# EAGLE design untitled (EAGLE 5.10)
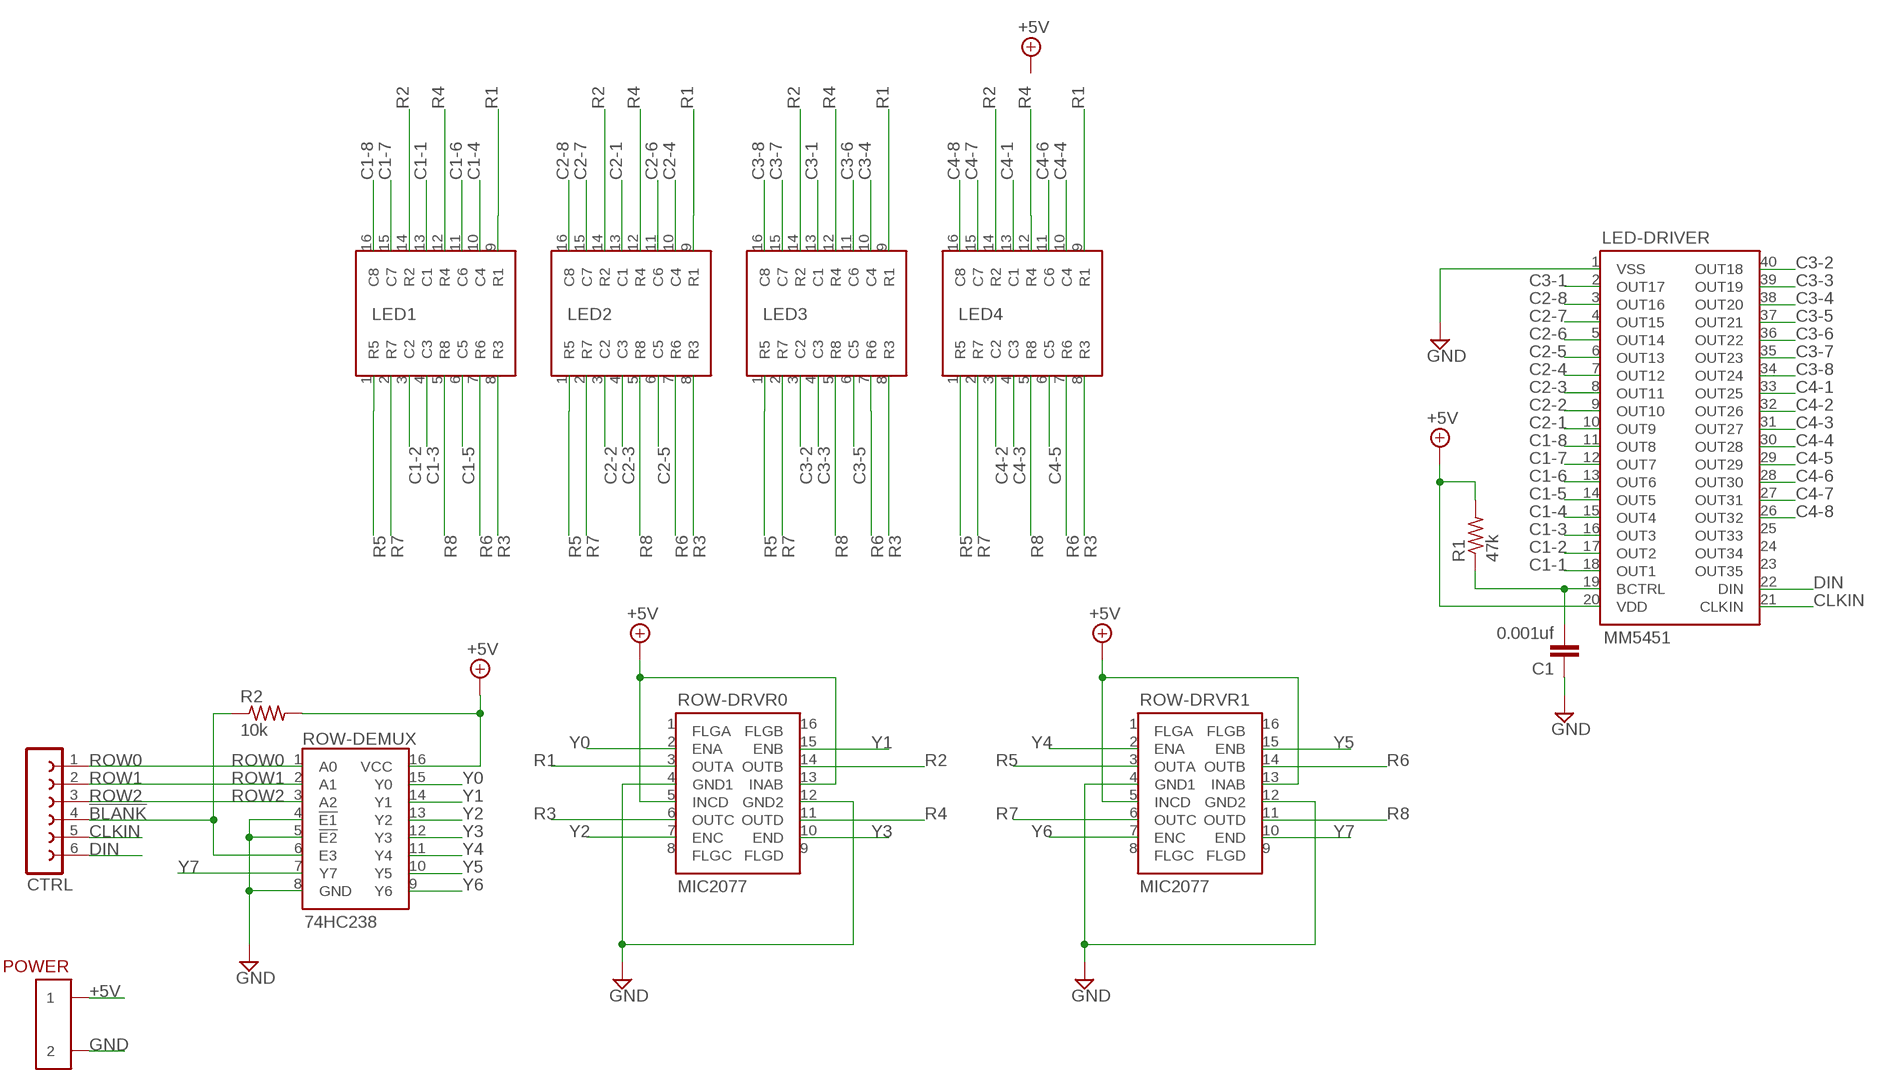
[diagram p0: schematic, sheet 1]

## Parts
C1  0.001uf  C-EU050-024X044  [C050-024X044]
CTRL  FE06-1  [FE06]
LED1  LED-MATRIX-8X8  [DIL16-6]
LED2  LED-MATRIX-8X8  [DIL16-6]
LED3  LED-MATRIX-8X8  [DIL16-6]
LED4  LED-MATRIX-8X8  [DIL16-6]
LED-DRIVER  MM5451  [DIL40-6]
POWER  SCREW-CLAMP-1.5  [SCREW-CLAMP-1.5]
R1  47k  R-US_0207/7  [0207/7]
R2  10k  R-US_M1206  [M1206]
ROW-DEMUX  74HC238  [DIL16-3]
ROW-DRVR0  MIC2077  [SO16]
ROW-DRVR1  MIC2077  [SO16]

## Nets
!BLANK: CTRL.4 R2.1 ROW-DEMUX.6(E3)
+5V: LED-DRIVER.20(VDD) POWER.1 R1.2 R2.2 ROW-DEMUX.16(VCC) ROW-DRVR0.5(INCD) ROW-DRVR0.13(INAB) ROW-DRVR1.5(INCD) ROW-DRVR1.13(INAB)
C1-1: LED1.13(C1) LED-DRIVER.18(OUT1)
C1-2: LED1.3(C2) LED-DRIVER.17(OUT2)
C1-3: LED1.4(C3) LED-DRIVER.16(OUT3)
C1-4: LED1.10(C4) LED-DRIVER.15(OUT4)
C1-5: LED1.6(C5) LED-DRIVER.14(OUT5)
C1-6: LED1.11(C6) LED-DRIVER.13(OUT6)
C1-7: LED1.15(C7) LED-DRIVER.12(OUT7)
C1-8: LED1.16(C8) LED-DRIVER.11(OUT8)
C2-1: LED2.13(C1) LED-DRIVER.10(OUT9)
C2-2: LED2.3(C2) LED-DRIVER.9(OUT10)
C2-3: LED2.4(C3) LED-DRIVER.8(OUT11)
C2-4: LED2.10(C4) LED-DRIVER.7(OUT12)
C2-5: LED2.6(C5) LED-DRIVER.6(OUT13)
C2-6: LED2.11(C6) LED-DRIVER.5(OUT14)
C2-7: LED2.15(C7) LED-DRIVER.4(OUT15)
C2-8: LED2.16(C8) LED-DRIVER.3(OUT16)
C3-1: LED3.13(C1) LED-DRIVER.2(OUT17)
C3-2: LED3.3(C2) LED-DRIVER.40(OUT18)
C3-3: LED3.4(C3) LED-DRIVER.39(OUT19)
C3-4: LED3.10(C4) LED-DRIVER.38(OUT20)
C3-5: LED3.6(C5) LED-DRIVER.37(OUT21)
C3-6: LED3.11(C6) LED-DRIVER.36(OUT22)
C3-7: LED3.15(C7) LED-DRIVER.35(OUT23)
C3-8: LED3.16(C8) LED-DRIVER.34(OUT24)
C4-1: LED4.13(C1) LED-DRIVER.33(OUT25)
C4-2: LED4.3(C2) LED-DRIVER.32(OUT26)
C4-3: LED4.4(C3) LED-DRIVER.31(OUT27)
C4-4: LED4.10(C4) LED-DRIVER.30(OUT28)
C4-5: LED4.6(C5) LED-DRIVER.29(OUT29)
C4-6: LED4.11(C6) LED-DRIVER.28(OUT30)
C4-7: LED4.15(C7) LED-DRIVER.27(OUT31)
C4-8: LED4.16(C8) LED-DRIVER.26(OUT32)
CLKIN: CTRL.5 LED-DRIVER.21(CLKIN)
DIN: CTRL.6 LED-DRIVER.22(DIN)
GND: C1.1 LED-DRIVER.1(VSS) POWER.2 ROW-DEMUX.4(!E1) ROW-DEMUX.5(!E2) ROW-DEMUX.8(GND) ROW-DRVR0.4(GND1) ROW-DRVR0.12(GND2) ROW-DRVR1.4(GND1) ROW-DRVR1.12(GND2)
N$1: C1.2 LED-DRIVER.19(BCTRL) R1.1
R1: LED1.9(R1) LED2.9(R1) LED3.9(R1) LED4.9(R1) ROW-DRVR0.3(OUTA)
R2: LED1.14(R2) LED2.14(R2) LED3.14(R2) LED4.14(R2) ROW-DRVR0.14(OUTB)
R3: LED1.8(R3) LED2.8(R3) LED3.8(R3) LED4.8(R3) ROW-DRVR0.6(OUTC)
R4: LED1.12(R4) LED2.12(R4) LED3.12(R4) LED4.12(R4) ROW-DRVR0.11(OUTD)
R5: LED1.1(R5) LED2.1(R5) LED3.1(R5) LED4.1(R5) ROW-DRVR1.3(OUTA)
R6: LED1.7(R6) LED2.7(R6) LED3.7(R6) LED4.7(R6) ROW-DRVR1.14(OUTB)
R7: LED1.2(R7) LED2.2(R7) LED3.2(R7) LED4.2(R7) ROW-DRVR1.6(OUTC)
R8: LED1.5(R8) LED2.5(R8) LED3.5(R8) LED4.5(R8) ROW-DRVR1.11(OUTD)
ROW0: CTRL.1 ROW-DEMUX.1(A0)
ROW1: CTRL.2 ROW-DEMUX.2(A1)
ROW2: CTRL.3 ROW-DEMUX.3(A2)
Y0: ROW-DEMUX.15(Y0) ROW-DRVR0.2(ENA)
Y1: ROW-DEMUX.14(Y1) ROW-DRVR0.15(ENB)
Y2: ROW-DEMUX.13(Y2) ROW-DRVR0.7(ENC)
Y3: ROW-DEMUX.12(Y3) ROW-DRVR0.10(END)
Y4: ROW-DEMUX.11(Y4) ROW-DRVR1.2(ENA)
Y5: ROW-DEMUX.10(Y5) ROW-DRVR1.15(ENB)
Y6: ROW-DEMUX.9(Y6) ROW-DRVR1.7(ENC)
Y7: ROW-DEMUX.7(Y7) ROW-DRVR1.10(END)
Unconnected: LED-DRIVER.23(OUT35) LED-DRIVER.24(OUT34) LED-DRIVER.25(OUT33) ROW-DRVR0.1(FLGA) ROW-DRVR0.8(FLGC) ROW-DRVR0.9(FLGD) ROW-DRVR0.16(FLGB) ROW-DRVR1.1(FLGA) ROW-DRVR1.8(FLGC) ROW-DRVR1.9(FLGD) ROW-DRVR1.16(FLGB)

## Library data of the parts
C1 = rcl:C-EU: CAPACITOR, European symbol
CTRL = con-lsta:FE06-1: FEMALE HEADER
LED1-LED4 = trl:LED-MATRIX-8X8
LED-DRIVER = trl:MM5451
POWER = trl:SCREW-CLAMP-1.5
R1 R2 = resistor:R-US_: RESISTOR, American symbol
ROW-DEMUX = trl:74HC238
ROW-DRVR0 ROW-DRVR1 = trl:MIC2077

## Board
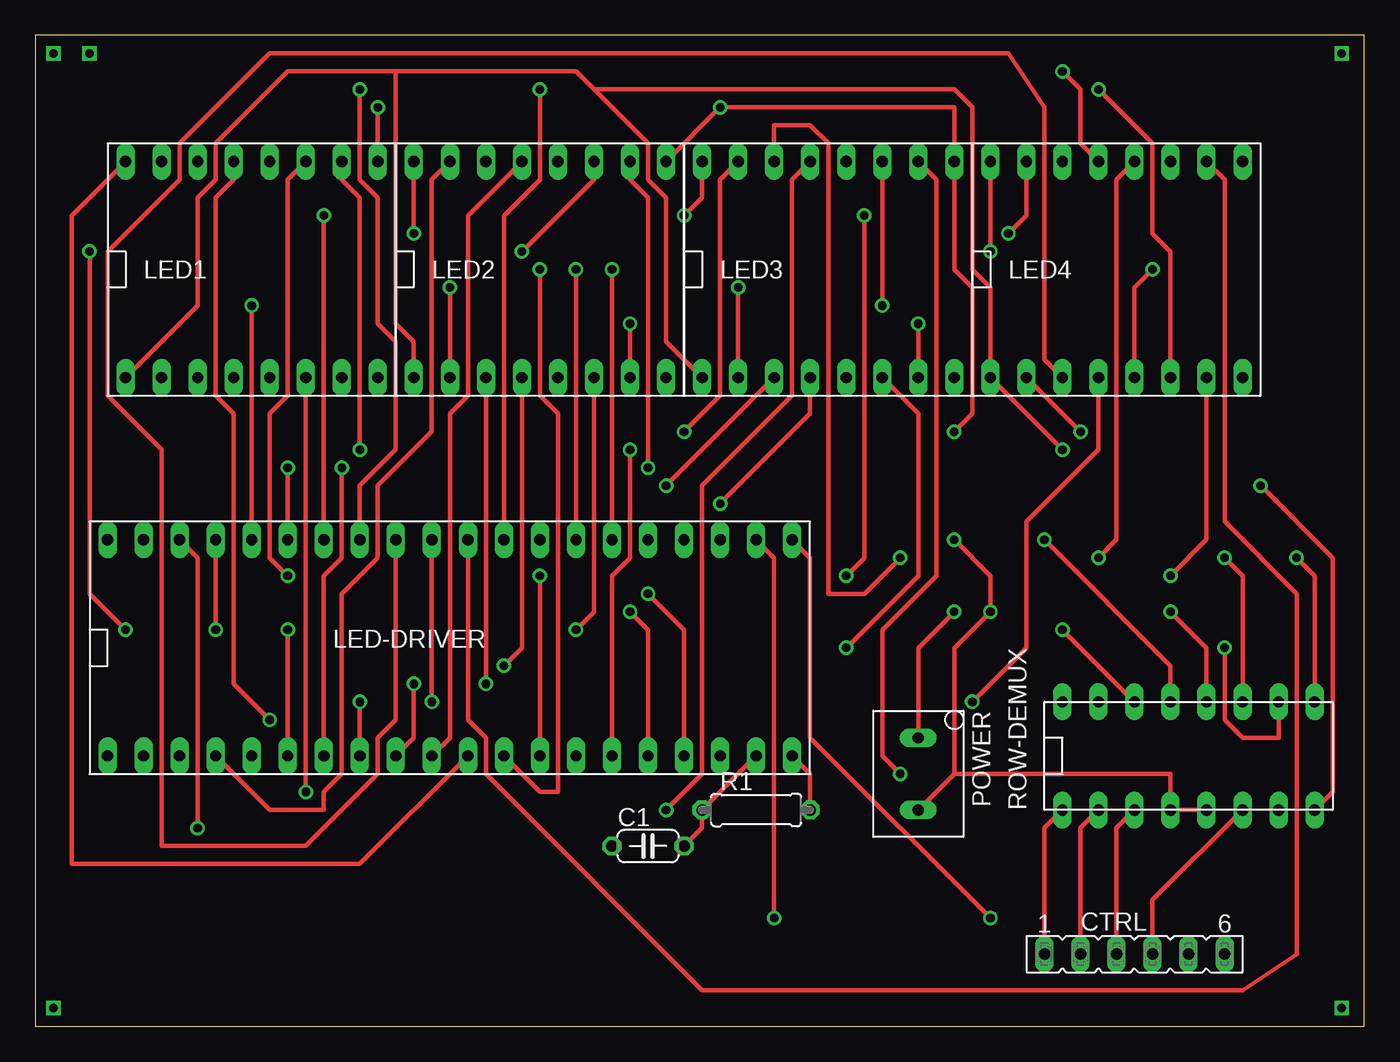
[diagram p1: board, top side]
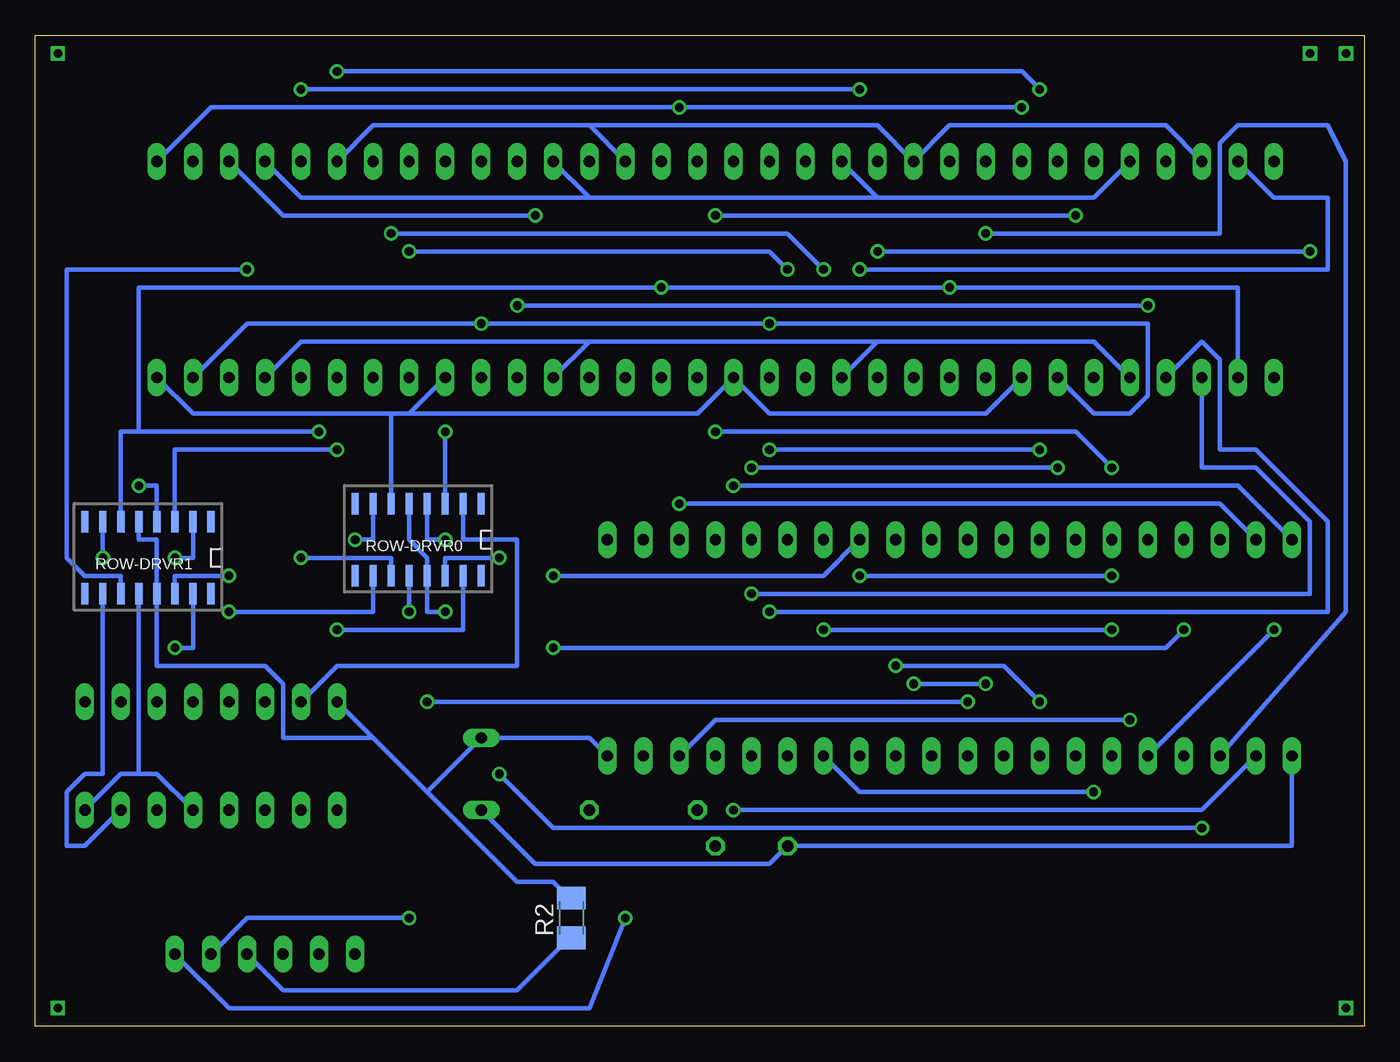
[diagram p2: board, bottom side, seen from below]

Size 93.65 x 69.84 mm. Coordinates in mm from the lower left corner, seen from the top.
Outline: 0,0 93.65,0 93.65,69.84 0,69.84 0,0
Copper layers (1*16): Top 0.035mm / dielectric 1.5mm / Bottom 0.035mm
Design rules "default *": minimum track width 12mil, minimum drill 24mil, track to track 10mil, track to pad 10mil, pad to pad 10mil, via to via 10mil, smd to smd 10mil, copper to edge 40mil, drill to drill 10mil, minimum pad ring 10mil, minimum via ring 8mil, stop-mask expansion 4mil, vias tented up to drill 0mil, thermal gap 10mil

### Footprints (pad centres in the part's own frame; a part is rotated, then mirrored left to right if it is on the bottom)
C050-024X044 = drill 0.813 octagon: 1 -2.54,0; 2 2.54,0
FE06 = drill 0.813 long: 1 -6.35,0; 2 -3.81,0; 3 -1.27,0; 4 1.27,0; 5 3.81,0; 6 6.35,0
DIL16-6 = drill 0.8 long: 1 -8.89,-7.62; 2 -6.35,-7.62; 3 -3.81,-7.62; 4 -1.27,-7.62; 5 1.27,-7.62; 6 3.81,-7.62; 7 6.35,-7.62; 8 8.89,-7.62; 9 8.89,7.62; 10 6.35,7.62; 11 3.81,7.62; 12 1.27,7.62; 13 -1.27,7.62; 14 -3.81,7.62; 15 -6.35,7.62; 16 -8.89,7.62
DIL40-6 = drill 0.8 long: 1 -7.62,24.13; 2 -7.62,21.59; 3 -7.62,19.05; 4 -7.62,16.51; 5 -7.62,13.97; 6 -7.62,11.43; 7 -7.62,8.89; 8 -7.62,6.35; 9 -7.62,3.81; 10 -7.62,1.27; 11 -7.62,-1.27; 12 -7.62,-3.81; 13 -7.62,-6.35; 14 -7.62,-8.89; 15 -7.62,-11.43; 16 -7.62,-13.97; 17 -7.62,-16.51; 18 -7.62,-19.05; 19 -7.62,-21.59; 20 -7.62,-24.13; 21 7.62,-24.13; 22 7.62,-21.59; 23 7.62,-19.05; 24 7.62,-16.51; 25 7.62,-13.97; 26 7.62,-11.43; 27 7.62,-8.89; 28 7.62,-6.35; 29 7.62,-3.81; 30 7.62,-1.27; 31 7.62,1.27; 32 7.62,3.81; 33 7.62,6.35; 34 7.62,8.89; 35 7.62,11.43; 36 7.62,13.97; 37 7.62,16.51; 38 7.62,19.05; 39 7.62,21.59; 40 7.62,24.13
SCREW-CLAMP-1.5 = drill 0.8 long: 1 -1.27,0; 2 3.81,0
0207/7 = drill 0.813 octagon: 1 -3.81,0; 2 3.81,0
M1206 = smd 1.6 x 2: 1 -1.4,0; 2 1.4,0
DIL16-3 = drill 0.8 long: 1 -3.81,8.89; 2 -3.81,6.35; 3 -3.81,3.81; 4 -3.81,1.27; 5 -3.81,-1.27; 6 -3.81,-3.81; 7 -3.81,-6.35; 8 -3.81,-8.89; 9 3.81,-8.89; 10 3.81,-6.35; 11 3.81,-3.81; 12 3.81,-1.27; 13 3.81,1.27; 14 3.81,3.81; 15 3.81,6.35; 16 3.81,8.89
SO16 = smd 0.508 x 1.524: 1 -3.81,-2.54; 2 -2.54,-2.54; 3 -1.27,-2.54; 4 0,-2.54; 5 1.27,-2.54; 6 2.54,-2.54; 7 3.81,-2.54; 8 5.08,-2.54; 9 5.08,2.54; 10 3.81,2.54; 11 2.54,2.54; 12 1.27,2.54; 13 0,2.54; 14 -1.27,2.54; 15 -2.54,2.54; 16 -3.81,2.54

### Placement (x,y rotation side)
C1  43.18,12.7 0 top
CTRL  77.47,5.08 0 top
LED1  15.24,53.34 0 top
LED2  35.56,53.34 0 top
LED3  55.88,53.34 0 top
LED4  76.2,53.34 0 top
LED-DRIVER  29.21,26.67 90 top
POWER  62.23,19.05 270 top
R1  50.8,15.24 0 top
R2  55.88,7.62 90 bottom
ROW-DEMUX  81.28,19.05 90 top
ROW-DRVR0  66.04,34.29 180 bottom
ROW-DRVR1  85.09,33.02 180 bottom

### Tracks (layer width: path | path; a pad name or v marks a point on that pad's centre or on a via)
!BLANK
  Top 0.305: ROW-DEMUX.6 78.74,8.89 CTRL.4
  Bottom 0.305: CTRL.4 76.2,2.54 59.69,2.54 55.88,6.35 R2.1
+5V  (via drill 0.61)
  Top 0.305: LED-DRIVER.20 54.61,17.78 R1.2 | v64.77,29.21 62.23,26.67 POWER.1
  Bottom 0.305: ROW-DRVR0.5 67.31,34.29 66.04,33.02 ROW-DRVR0.13 66.04,29.21 v64.77,29.21 | ROW-DRVR1.5 86.36,34.29 85.09,34.29 ROW-DRVR1.13 85.09,25.4 77.47,25.4 76.2,24.13 76.2,20.32 69.85,20.32 | 69.85,20.32 ROW-DEMUX.16 | 66.04,16.51 69.85,20.32 | 66.04,16.51 59.69,10.16 57.15,10.16 55.88,8.89 R2.2 | 66.04,16.51 POWER.1 54.61,20.32 LED-DRIVER.20
C1-1  (via drill 0.61)
  Top 0.305: v16.51,21.59 13.97,24.13 13.97,43.18 12.7,44.45 12.7,58.42 13.97,59.69 LED1.13
  Bottom 0.305: LED-DRIVER.18 45.72,21.59 v16.51,21.59
C1-2  (via drill 0.61)
  Top 0.305: v43.18,30.48 45.72,27.94 LED-DRIVER.17
  Bottom 0.305: LED1.3 11.43,39.37 7.62,39.37 3.81,35.56 3.81,30.48 v43.18,30.48
C1-3  (via drill 0.61)
  Top 0.305: v41.91,29.21 43.18,27.94 LED-DRIVER.16
  Bottom 0.305: LED1.4 11.43,48.26 10.16,46.99 10.16,40.64 7.62,40.64 2.54,35.56 2.54,29.21 v41.91,29.21
C1-4  (via drill 0.61)
  Top 0.305: LED-DRIVER.15 40.64,31.75 41.91,33.02 v41.91,40.64 | v22.86,40.64 22.86,58.42 21.59,59.69 LED1.10
  Bottom 0.305: v41.91,40.64 v22.86,40.64
C1-5  (via drill 0.61)
  Top 0.305: v19.05,16.51 LED1.6
  Bottom 0.305: LED-DRIVER.14 35.56,16.51 v19.05,16.51
C1-6  (via drill 0.61)
  Top 0.305: v35.56,31.75 LED-DRIVER.13 | v17.78,31.75 16.51,33.02 16.51,43.18 17.78,44.45 17.78,59.69 LED1.11
  Bottom 0.305: v17.78,31.75 v35.56,31.75
C1-7  (via drill 0.61)
  Top 0.305: LED-DRIVER.12 35.56,16.51 36.83,16.51 36.83,43.18 35.56,44.45 v35.56,53.34
  Bottom 0.305: v35.56,53.34 2.54,53.34 2.54,58.42 6.35,58.42 LED1.15
C1-8
  Top 0.305: LED-DRIVER.11 22.86,11.43 2.54,11.43 2.54,57.15 LED1.16
C2-1
  Top 0.305: LED-DRIVER.10 29.21,20.32 29.21,43.18 30.48,44.45 30.48,57.15 LED2.13
C2-2  (via drill 0.61)
  Top 0.305: LED-DRIVER.9 26.67,20.32 v26.67,24.13 | v31.75,24.13 LED2.3
  Bottom 0.305: v26.67,24.13 v31.75,24.13
C2-3  (via drill 0.61)
  Top 0.305: LED-DRIVER.8 v22.86,22.86 | v33.02,25.4 34.29,26.67 LED2.4
  Bottom 0.305: v22.86,22.86 25.4,25.4 v33.02,25.4
C2-4  (via drill 0.61)
  Top 0.305: LED-DRIVER.7 20.32,31.75 21.59,33.02 v21.59,39.37 | v43.18,39.37 43.18,58.42 41.91,59.69 LED2.10
  Bottom 0.305: v21.59,39.37 v43.18,39.37
C2-5  (via drill 0.61)
  Top 0.305: LED-DRIVER.6 v17.78,27.94 | v38.1,27.94 39.37,29.21 LED2.6
  Bottom 0.305: v17.78,27.94 v38.1,27.94
C2-6  (via drill 0.61)
  Top 0.305: v6.35,27.94 3.81,30.48 v3.81,54.61 | v34.29,54.61 39.37,59.69 LED2.11
  Bottom 0.305: LED-DRIVER.5 v6.35,27.94 | v3.81,54.61 v34.29,54.61
C2-7
  Top 0.305: LED-DRIVER.4 16.51,15.24 20.32,15.24 20.32,16.51 21.59,17.78 21.59,30.48 24.13,33.02 24.13,38.1 27.94,41.91 27.94,59.69 LED2.15
C2-8  (via drill 0.61)
  Top 0.305: v26.67,55.88 LED2.16
  Bottom 0.305: LED-DRIVER.3 1.27,29.21 1.27,60.96 2.54,63.5 8.89,63.5 10.16,62.23 10.16,55.88 v26.67,55.88
C3-1  (via drill 0.61)
  Top 0.305: v44.45,15.24 46.99,17.78 46.99,38.1 53.34,44.45 53.34,59.69 LED3.13
  Bottom 0.305: LED-DRIVER.2 11.43,15.24 v44.45,15.24
C3-2  (via drill 0.61)
  Top 0.305: v44.45,38.1 LED3.3
  Bottom 0.305: LED-DRIVER.40 8.89,38.1 v44.45,38.1
C3-3  (via drill 0.61)
  Top 0.305: v48.26,36.83 54.61,43.18 LED3.4
  Bottom 0.305: LED-DRIVER.39 10.16,36.83 v48.26,36.83
C3-4  (via drill 0.61)
  Top 0.305: LED-DRIVER.38 11.43,33.02 v11.43,13.97 | v60.96,17.78 59.69,19.05 59.69,27.94 63.5,31.75 63.5,59.69 LED3.10
  Bottom 0.305: v11.43,13.97 57.15,13.97 v60.96,17.78
C3-5  (via drill 0.61)
  Top 0.305: v12.7,27.94 LED-DRIVER.37 | v57.15,26.67 62.23,31.75 62.23,43.18 LED3.6
  Bottom 0.305: v12.7,27.94 13.97,26.67 v57.15,26.67
C3-6  (via drill 0.61)
  Top 0.305: LED-DRIVER.36 v15.24,50.8 | v59.69,50.8 LED3.11
  Bottom 0.305: v15.24,50.8 v59.69,50.8
C3-7  (via drill 0.61)
  Top 0.305: LED-DRIVER.35 v17.78,39.37 | v45.72,41.91 48.26,44.45 48.26,59.69 LED3.15
  Bottom 0.305: v17.78,39.37 20.32,41.91 v45.72,41.91
C3-8  (via drill 0.61)
  Top 0.305: LED-DRIVER.34 v20.32,57.15 | v45.72,57.15 46.99,58.42 LED3.16
  Bottom 0.305: v20.32,57.15 v45.72,57.15
C4-1  (via drill 0.61)
  Top 0.305: LED-DRIVER.33 22.86,38.1 25.4,40.64 25.4,48.26 24.13,49.53 24.13,58.42 22.86,59.69 v22.86,66.04 | v72.39,67.31 73.66,66.04 73.66,62.23 LED4.13
  Bottom 0.305: v22.86,66.04 24.13,67.31 v72.39,67.31
C4-2
  Top 0.305: LED-DRIVER.32 25.4,21.59 24.13,20.32 24.13,17.78 19.05,12.7 8.89,12.7 8.89,40.64 5.08,44.45 5.08,54.61 10.16,59.69 10.16,62.23 16.51,68.58 68.58,68.58 71.12,64.77 71.12,46.99 LED4.3
C4-3  (via drill 0.61)
  Top 0.305: v27.94,22.86 LED-DRIVER.31 | v66.04,22.86 69.85,26.67 69.85,35.56 74.93,40.64 LED4.4
  Bottom 0.305: v27.94,22.86 v66.04,22.86
C4-4
  Top 0.305: LED-DRIVER.30 30.48,21.59 31.75,20.32 31.75,17.78 46.99,2.54 85.09,2.54 88.9,5.08 88.9,30.48 83.82,35.56 83.82,59.69 LED4.10
C4-5  (via drill 0.61)
  Top 0.305: LED-DRIVER.29 33.02,57.15 35.56,59.69 v35.56,66.04 | v74.93,66.04 78.74,62.23 78.74,55.88 80.01,54.61 LED4.6
  Bottom 0.305: v35.56,66.04 v74.93,66.04
C4-6  (via drill 0.61)
  Top 0.305: v57.15,31.75 58.42,33.02 v58.42,57.15
  Bottom 0.305: LED-DRIVER.28 38.1,31.75 v57.15,31.75 | v58.42,57.15 76.2,57.15 LED4.11
C4-7  (via drill 0.61)
  Top 0.305: LED-DRIVER.27 v38.1,53.34 | v68.58,55.88 69.85,57.15 LED4.15
  Bottom 0.305: v38.1,53.34 40.64,55.88 v68.58,55.88
C4-8  (via drill 0.61)
  Top 0.305: LED-DRIVER.26 v40.64,53.34 | v67.31,54.61 LED4.16
  Bottom 0.305: v40.64,53.34 41.91,54.61 v67.31,54.61
CLKIN  (via drill 0.61)
  Top 0.305: LED-DRIVER.21 54.61,33.02 54.61,20.32 v67.31,7.62
  Bottom 0.305: v67.31,7.62 78.74,7.62 CTRL.5
DIN  (via drill 0.61)
  Top 0.305: LED-DRIVER.22 52.07,33.02 v52.07,7.62
  Bottom 0.305: v52.07,7.62 54.61,1.27 80.01,1.27 CTRL.6
GND  (via drill 0.61)
  Top 0.305: 64.77,17.78 64.77,26.67 v67.31,29.21 ROW-DRVR0.12 v64.77,34.29 | POWER.2 64.77,17.78 | ROW-DEMUX.5 ROW-DEMUX.4 80.01,17.78 64.77,17.78 | v86.36,38.1 91.44,33.02 91.44,16.51 ROW-DEMUX.8
  Bottom 0.305: LED-DRIVER.1 5.08,12.7 C1.1 41.91,11.43 58.42,11.43 POWER.2 | v67.31,29.21 ROW-DRVR0.12 | ROW-DRVR0.4 66.04,34.29 v64.77,34.29 | 86.36,17.78 ROW-DRVR1.12 | 86.36,17.78 85.09,17.78 ROW-DEMUX.5 | ROW-DRVR1.4 85.09,38.1 v86.36,38.1 | 86.36,17.78 87.63,17.78 ROW-DEMUX.8
N$1
  Top 0.305: LED-DRIVER.19 R1.1 46.99,13.97 C1.2
N$5  (via drill 0.6)
  other vias: 1.27,68.58
N$6  (via drill 0.6)
  other vias: 3.81,68.58
N$7  (via drill 0.6)
  other vias: 92.08,68.58
N$8  (via drill 0.6)
  other vias: 92.08,1.27
N$9  (via drill 0.6)
  other vias: 1.27,1.27
R1  (via drill 0.61)
  Top 0.305: v64.77,41.91 66.04,43.18 66.04,52.07 64.77,53.34 LED3.9 64.77,64.77 v48.26,64.77 LED2.9 | LED1.9 v24.13,64.77
  Bottom 0.305: v64.77,41.91 ROW-DRVR0.3 | v24.13,64.77 v48.26,64.77 81.28,64.77 LED4.9
R2  (via drill 0.61)
  Top 0.305: v60.96,33.02 58.42,30.48 55.88,30.48 55.88,62.23 54.61,63.5 52.07,63.5 LED3.14
  Bottom 0.305: LED1.14 13.97,63.5 29.21,63.5 LED2.14 34.29,63.5 54.61,63.5 | ROW-DRVR0.14 64.77,33.02 v60.96,33.02 | LED4.14 69.85,63.5 54.61,63.5 | 54.61,63.5 LED3.14
R3
  Bottom 0.305: LED1.8 26.67,43.18 41.91,43.18 LED2.8 46.99,43.18 67.31,43.18 | 68.58,43.18 ROW-DRVR0.6 | 67.31,43.18 68.58,43.18 | 67.31,43.18 LED3.8 | LED4.8 82.55,43.18 68.58,43.18
R4  (via drill 0.61)
  Top 0.305: v74.93,33.02 76.2,34.29 76.2,59.69 LED4.12
  Bottom 0.305: ROW-DRVR0.11 68.58,33.02 v74.93,33.02 | LED1.12 19.05,58.42 34.29,58.42 | 34.29,58.42 LED2.12 | 54.61,58.42 LED3.12 | 34.29,58.42 54.61,58.42 | LED4.12 74.93,58.42 54.61,58.42
R5  (via drill 0.61)
  Top 0.305: v72.39,40.64 LED4.1 67.31,52.07 66.04,53.34 66.04,64.77 64.77,66.04 39.37,66.04 | LED1.1 11.43,50.8 11.43,58.42 12.7,59.69 12.7,62.23 17.78,67.31 25.4,67.31 | 25.4,67.31 25.4,49.53 26.67,48.26 LED2.1 | LED3.1 44.45,48.26 44.45,58.42 43.18,59.69 43.18,62.23 39.37,66.04 | 39.37,66.04 38.1,67.31 25.4,67.31
  Bottom 0.305: ROW-DRVR1.3 83.82,40.64 v72.39,40.64
R6  (via drill 0.61)
  Top 0.305: v80.01,31.75 82.55,34.29 LED4.7 | v41.91,49.53 LED2.7 | v62.23,49.53 LED3.7
  Bottom 0.305: ROW-DRVR1.14 83.82,31.75 v80.01,31.75 | LED1.7 19.05,43.18 16.51,43.18 15.24,44.45 15.24,49.53 v41.91,49.53 v62.23,49.53 78.74,49.53 LED4.7
R7  (via drill 0.61)
  Top 0.305: v73.66,41.91 LED4.2 | v29.21,52.07 LED2.2 | v49.53,52.07 LED3.2
  Bottom 0.305: ROW-DRVR1.6 87.63,41.91 86.36,41.91 | 86.36,41.91 v73.66,41.91 | LED1.2 8.89,52.07 v29.21,52.07 v49.53,52.07 86.36,52.07 86.36,41.91
R8  (via drill 0.61)
  Top 0.305: v78.74,53.34 77.47,52.07 LED4.5
  Bottom 0.305: ROW-DRVR1.11 87.63,31.75 90.17,31.75 91.44,33.02 91.44,53.34 v78.74,53.34 | LED1.5 19.05,48.26 34.29,48.26 | 34.29,48.26 LED2.5 | 54.61,48.26 LED3.5 | 34.29,48.26 54.61,48.26 | LED4.5 74.93,48.26 54.61,48.26
ROW0
  Top 0.305: ROW-DEMUX.1 71.12,13.97 CTRL.1
ROW1
  Top 0.305: ROW-DEMUX.2 73.66,13.97 CTRL.2
ROW2
  Top 0.305: ROW-DEMUX.3 76.2,13.97 CTRL.3
Y0
  Bottom 0.305: ROW-DRVR0.2 63.5,34.29 59.69,34.29 59.69,25.4 72.39,25.4 ROW-DEMUX.15
Y1  (via drill 0.61)
  Top 0.305: v72.39,27.94 ROW-DEMUX.14
  Bottom 0.305: ROW-DRVR0.15 63.5,27.94 v72.39,27.94
Y2  (via drill 0.61)
  Top 0.305: v71.12,34.29 80.01,25.4 ROW-DEMUX.13
  Bottom 0.305: ROW-DRVR0.7 69.85,34.29 v71.12,34.29
Y3  (via drill 0.61)
  Top 0.305: v80.01,29.21 82.55,26.67 ROW-DEMUX.12
  Bottom 0.305: ROW-DRVR0.10 69.85,29.21 v80.01,29.21
Y4  (via drill 0.61)
  Top 0.305: v83.82,33.02 85.09,31.75 ROW-DEMUX.11
  Bottom 0.305: ROW-DRVR1.2 82.55,33.02 v83.82,33.02
Y5  (via drill 0.61)
  Top 0.305: v83.82,26.67 83.82,21.59 85.09,20.32 87.63,20.32 ROW-DEMUX.10
  Bottom 0.305: ROW-DRVR1.15 82.55,26.67 v83.82,26.67
Y6  (via drill 0.61)
  Top 0.305: v88.9,33.02 90.17,31.75 ROW-DEMUX.9
  Bottom 0.305: v88.9,33.02 ROW-DRVR1.7
Y7
  Bottom 0.305: ROW-DRVR1.10 88.9,17.78 90.17,17.78 91.44,16.51 91.44,12.7 90.17,12.7 ROW-DEMUX.7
